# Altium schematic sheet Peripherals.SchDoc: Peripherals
size A4; DocumentNumber: MB1165; Revision: C.1; SheetNumber: 12; SheetTotal: 17; Project: STM32469I-EVAL
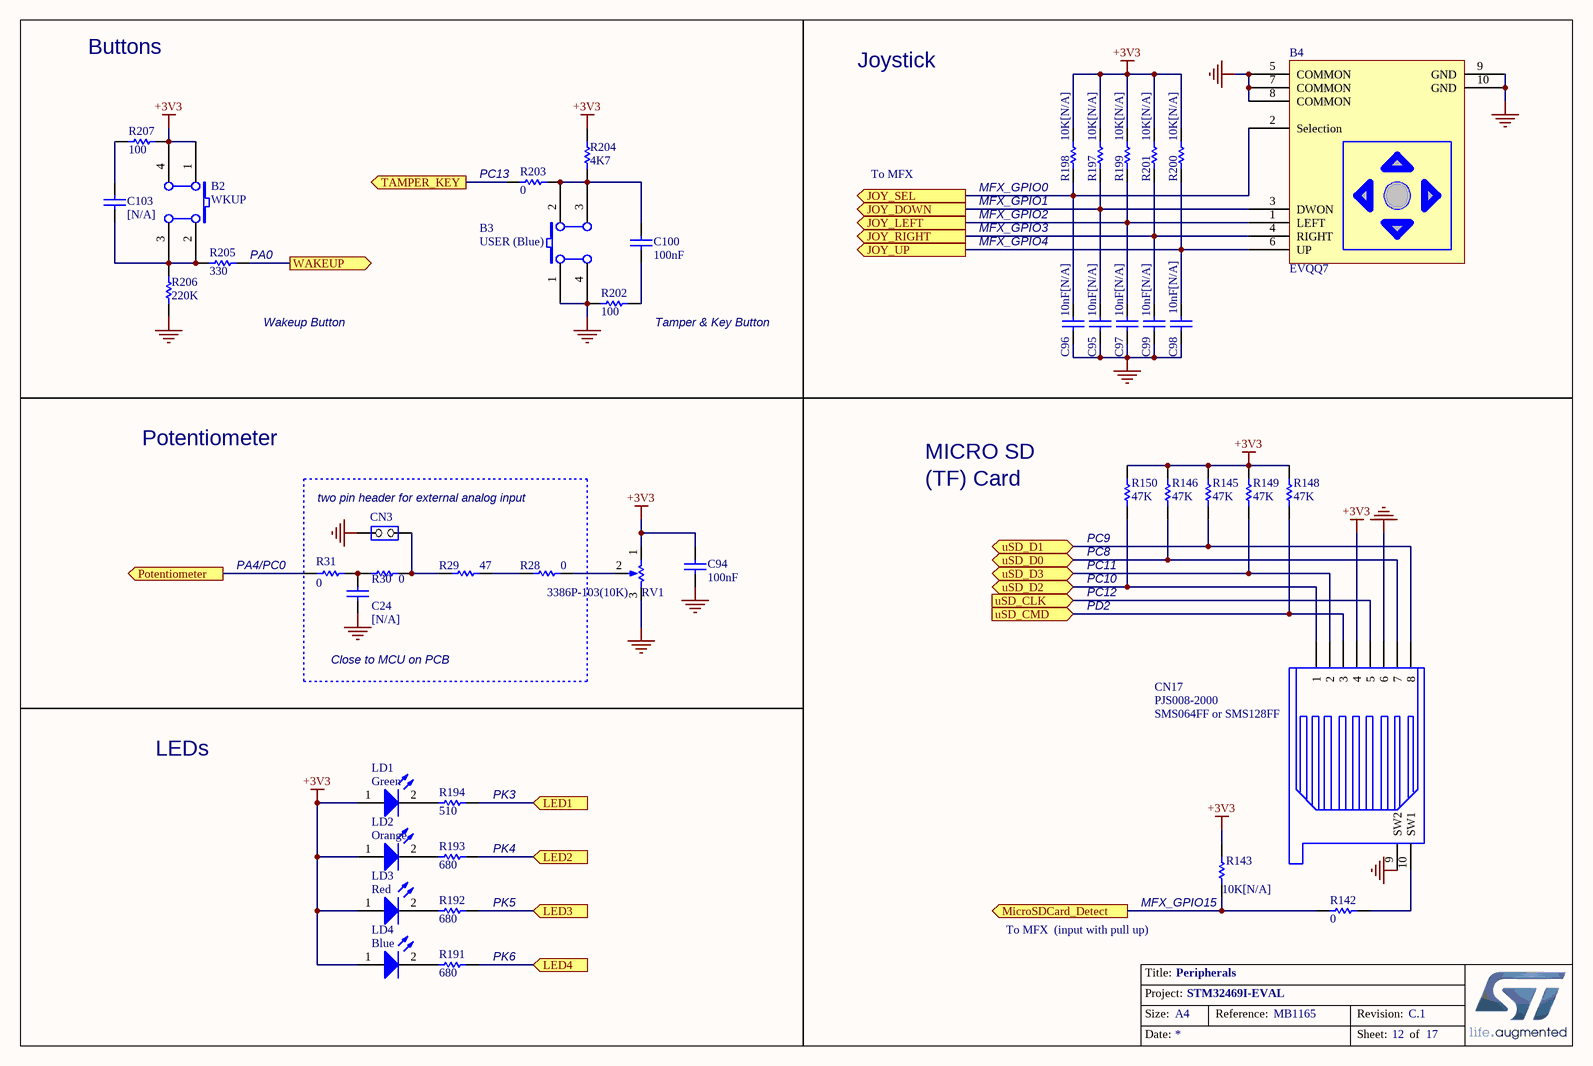
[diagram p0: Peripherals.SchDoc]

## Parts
B2  WKUP  [PB10]
B3  USER (Blue)  [PB10]
B4  EVQQ7  [SW-JOY]
C24  [N/A]  [0603C]
C94  100nF  [0603C]
C95  10nF[N/A]  [0603C]
C96  10nF[N/A]  [0603C]
C97  10nF[N/A]  [0603C]
C98  10nF[N/A]  [0603C]
C99  10nF[N/A]  [0603C]
C100  100nF  [0603C]
C103  [N/A]  [0603C]
CN3  (no value)  [SIP2]
CN17  PJS008-2000  [MSD_PJS008_]
LD1  Green  [0603D]
LD2  Orange  [0603D]
LD3  Red  [0603D]
LD4  Blue  [0603D]
R28  0  [0603R]
R29  47  [0603R]
R30  0  [0603R]
R31  0  [0603R]
R142  0  [0603R]
R143  10K[N/A]  [0603R]
R145  47K  [0603R]
R146  47K  [0603R]
R148  47K  [0603R]
R149  47K  [0603R]
R150  47K  [0603R]
R191  680  [0603R]
R192  680  [0603R]
R193  680  [0603R]
R194  510  [0603R]
R197  10K[N/A]  [0603R]
R198  10K[N/A]  [0603R]
R199  10K[N/A]  [0603R]
R200  10K[N/A]  [0603R]
R201  10K[N/A]  [0603R]
R202  100  [0603R]
R203  0  [0603R]
R204  4K7  [0603R]
R205  330  [0603R]
R206  220K  [0603R]
R207  100  [0603R]
RV1  3386P-103(10K)  [3386P]

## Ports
JOY_DOWN (out), JOY_LEFT (out), JOY_RIGHT (out), JOY_SEL (out), JOY_UP (out), LED1 (in), LED2 (in), LED3 (in), LED4 (in), MicroSDCard_Detect (out), Potentiometer (out), TAMPER_KEY (out), uSD_CLK (in), uSD_CMD (in), uSD_D0 (bidir), uSD_D1 (bidir), uSD_D2 (bidir), uSD_D3 (bidir), WAKEUP (out)

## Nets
+3V3: B2.1(A0) B2.4(A1) C94.1 CN17.4 LD1.1(A) LD2.1(A) LD3.1(A) LD4.1(A) R143.2 R145.1 R146.1 R148.1 R149.1 R150.1 R197.1 R198.1 R199.1 R200.1 R201.1 R204.2 R207.1 RV1.1(BOT)
GND: B3.1(A0) B3.4(A1) B4.5(COMMON) B4.7(COMMON) B4.8(COMMON) B4.9(GND) B4.10(GND) C24.1 C94.2 C95.1 C96.1 C97.1 C98.1 C99.1 CN3.2(NO) CN17.6 CN17.9(SW2) R202.1 R206.2 RV1.3(TOP)
JOY_DOWN: B4.3(DWON) C95.2 R197.2 ; port JOY_DOWN
JOY_LEFT: B4.1(LEFT) C97.2 R199.2 ; port JOY_LEFT
JOY_RIGHT: B4.4(RIGHT) C99.2 R201.2 ; port JOY_RIGHT
JOY_SEL: B4.2(Selection) C96.2 R198.2 ; port JOY_SEL
JOY_UP: B4.6(UP) C98.2 R200.2 ; port JOY_UP
LED1: R194.1 ; port LED1
LED2: R193.1 ; port LED2
LED3: R192.1 ; port LED3
LED4: R191.1 ; port LED4
MicroSDCard_Detect: R142.1 R143.1 ; port MicroSDCard_Detect
Potentiometer: R31.2 ; port Potentiometer
TAMPER_KEY: R203.2 ; port TAMPER_KEY
uSD_CLK: CN17.5 ; port uSD_CLK
uSD_CMD: CN17.3 R148.2 ; port uSD_CMD
uSD_D0: CN17.7 R146.2 ; port uSD_D0
uSD_D1: CN17.8 R145.2 ; port uSD_D1
uSD_D2: CN17.1 R150.2 ; port uSD_D2
uSD_D3: CN17.2 R149.2 ; port uSD_D3
WAKEUP: R205.2 ; port WAKEUP
NetB2_2: B2.2(B0) B2.3(B1) C103.2 R205.1 R206.1
NetB3_2: B3.2(B0) B3.3(B1) C100.2 R203.1 R204.1
NetC24_2: C24.2 R30.1 R31.1
NetC100_1: C100.1 R202.2
NetC103_1: C103.1 R207.2
NetCN3_1: CN3.1(COMMON) R29.1 R30.2
NetCN17_10: CN17.10(SW1) R142.2
NetLD1_2: LD1.2(K) R194.2
NetLD2_2: LD2.2(K) R193.2
NetLD3_2: LD3.2(K) R192.2
NetLD4_2: LD4.2(K) R191.2
NetR28_1: R28.1 R29.2
NetR28_2: R28.2 RV1.2(TAP)

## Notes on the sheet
- Buttons
- Joystick
- (near R203) PC13
- To MFX
- (near R198) MFX_GPIO0
- (near R205) PA0
- MFX_GPIO1
- MFX_GPIO2
- MFX_GPIO3
- MFX_GPIO4
- Wakeup Button
- (near R202) Tamper & Key Button
- Potentiometer
- MICRO SD
- (near CN3) two pin header for external analog input
- (TF) Card
- (near R31) PA4/PC0
- (near R150) PC8
- (near R150) PC9
- PC10
- PC11
- PC12
- Close to MCU on PCB
- PD2
- (near CN17) SMS064FF or SMS128FF
- LEDs
- (near R194) PK3
- (near R193) PK4
- (near R192) PK5
- To MFX  (input with pull up)
- (near R143) MFX_GPIO15
- (near R191) PK6

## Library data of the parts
B2 B3 = SW PUSHBUTTON: SE PUSHBUTTON
C24 = cap: Capacitor; Value: 100pF
C94-C100 C103 = CAP: Capacitor; Value: 100pF
CN3 = JP2
CN17 = SMS016AFA5E
LD1-LD4 = LED2: Typical RED, GREEN, YELLOW, AMBER GaAs LED
R28-R31 R142 R143 R191-R194 R202 R203 R205 R207 = Res1: Resistor; Value: 1K
R145 R146 R148-R150 R197-R201 R204 R206 = res1: Resistor; Value: 1K
RV1 = RV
